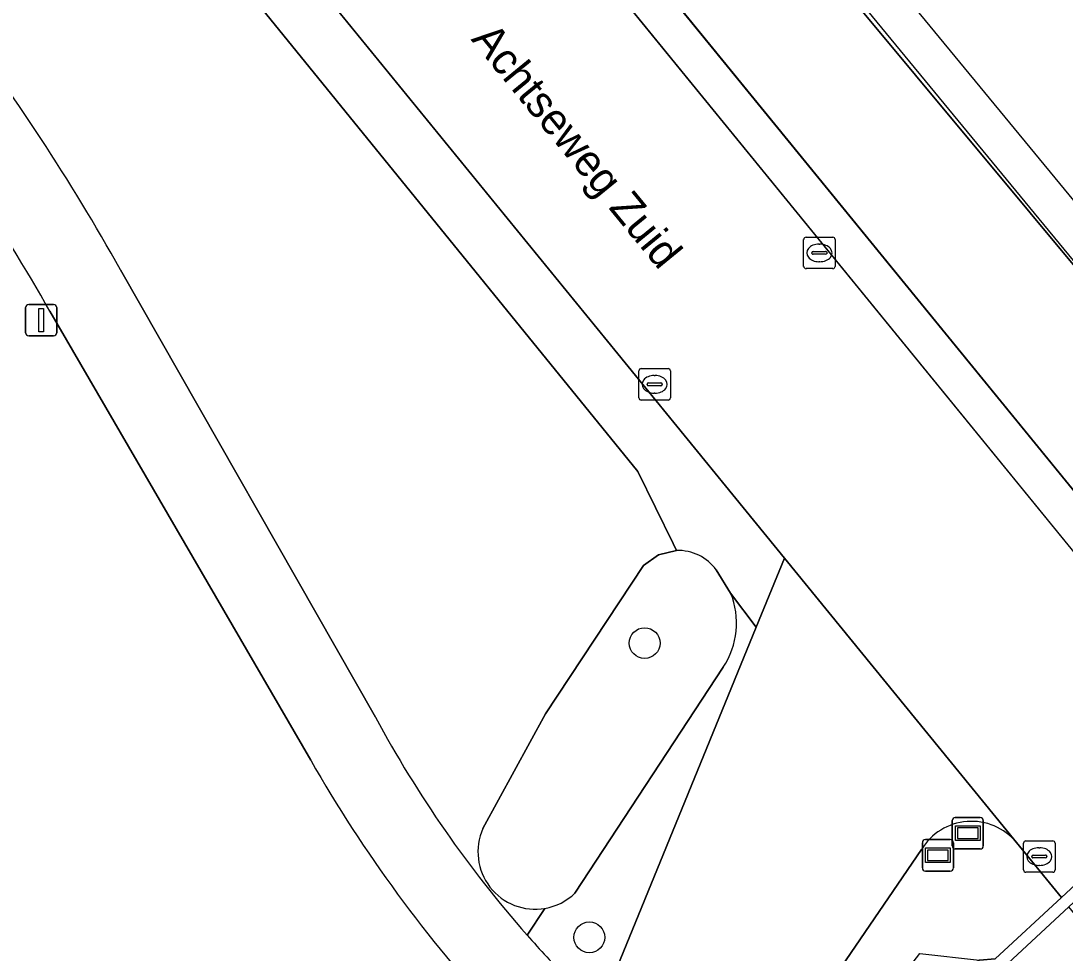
# Model space of a CAD drawing. Extents: x 157132 to 159279, y 384991 to 386650.
# Drawn here: x 159129.42 to 159162.63, y 385372.27 to 385401.9 of the extents above; entities that cross this region are included whole.
import ezdxf

# ---------------------------------------------------------------- set-up
doc = ezdxf.new("R2010")
doc.units = 0
for name, color, linetype in [('IMGEO_Boom', 7, 'Continuous'), ('IMGEO_Fietspad_gesloten', 7, 'Continuous'), ('IMGEO_Gemengd_bos', 7, 'Continuous'), ('IMGEO_Grasland_overig', 7, 'Continuous'), ('IMGEO_Groenvoorziening', 7, 'Continuous'), ('IMGEO_Hek', 7, 'Continuous'), ('IMGEO_Informatiebord', 7, 'Continuous'), ('IMGEO_Kolk', 7, 'Continuous'), ('IMGEO_Lichtmast', 7, 'Continuous'), ('IMGEO_Muur', 7, 'Continuous'), ('IMGEO_Openbare_ruimte_label', 7, 'Continuous'), ('IMGEO_Rijbaan_lokaal_open', 7, 'Continuous'), ('IMGEO_Spoorbaan_halfverhard', 7, 'Continuous'), ('IMGEO_Terreindeel_open', 7, 'Continuous'), ('IMGEO_Voetpad_open', 7, 'Continuous'), ('IMGEO_Waterloop', 7, 'Continuous')]:
    doc.layers.add(name, color=color, linetype=linetype)

msp = doc.modelspace()

# ---------------------------------------------------------------- linework, layer by layer
at = {"layer": 'IMGEO_Boom'}
for centre in [(159149.26, 385382.121), (159147.502, 385372.767)]:
    msp.add_circle(centre, 0.489, dxfattribs=at)
at = {"layer": 'IMGEO_Fietspad_gesloten'}
for points in [[(159140.697, 385379.765), (159132.59, 385393.989)], [(159130.342, 385392.676), (159138.639, 385378.397)]]:
    msp.add_lwpolyline(points, dxfattribs=at)
for centre, radius, start, end in [((159070.174, 385358.967), 71.57, 29.29683, 37.11613), ((159064.342, 385355.135), 75.929, 29.63123, 36.69187), ((159173.415, 385397.405), 37.17, 208.3324, 221.3679), ((159177.232, 385400.446), 44.448, 209.7395, 222.8211), ((159173.878, 385397.84), 37.805, 221.3976, 224.2452)]:
    msp.add_arc(centre, radius, start, end, dxfattribs=at)
at = {"layer": 'IMGEO_Gemengd_bos'}
for points in [[(159144.117, 385376.225), (159146.108, 385379.875), (159149.225, 385384.585), (159149.701, 385384.93), (159150.273, 385385.066), (159150.167, 385385.283), (159149.043, 385387.58), (159057.676, 385500), (159035.861, 385526.812), (159000, 385569.989), (158976.812, 385598.387), (158944.195, 385637.794), (158939.671, 385643.611), (158934.261, 385635.792)], [(159132.59, 385393.989), (159140.697, 385379.765)], [(159138.639, 385378.397), (159130.342, 385392.676)], [(159153.481, 385365.728), (159153.796, 385366.759), (159158.017, 385372.254), (159159.908, 385372.041), (159160.412, 385372.085), (159162.514, 385374.032), (159161.083, 385375.787)], [(159158.064, 385375.556), (159151.636, 385366.142), (159166.215, 385350.114), (159185.472, 385329.661), (159187.671, 385327.321)], [(159145.519, 385372.84), (159146.09, 385373.688)], [(159191.433, 385324.723), (159192.248, 385324.356), (159202.706, 385324.094), (159195.643, 385333.405), (159162.754, 385373.737), (159160.671, 385371.807), (159160.588, 385371.307), (159160.64, 385370.549), (159156.274, 385364.359)]]:
    msp.add_lwpolyline(points, dxfattribs=at)
for centre, radius, start, end in [((159070.174, 385358.967), 71.57, 29.29683, 37.11613), ((159064.342, 385355.135), 75.929, 29.63123, 36.69187), ((159173.415, 385397.405), 37.17, 208.3324, 221.3679), ((159177.232, 385400.446), 44.448, 209.7395, 222.8211), ((159159.656, 385374.597), 1.858, 39.8124, 148.9385), ((159145.778, 385375.481), 1.82, 155.8671, 279.8766)]:
    msp.add_arc(centre, radius, start, end, dxfattribs=at)
at = {"layer": 'IMGEO_Grasland_overig'}
for points in [[(159070.687, 385500), (159100.286, 385463.691), (159167.2, 385381.706), (159167.226, 385381.955), (159168.723, 385381.796), (159169.657, 385380.664), (159169.912, 385380.355), (159170.761, 385379.326), (159170.605, 385377.81), (159170.356, 385377.836), (159191.002, 385351.917), (159224.612, 385309.725)], [(159218.546, 385326.665), (159205.058, 385342.95), (159195.791, 385354.347), (159181.227, 385371.527), (159168.76, 385387.107), (159146.986, 385413.255), (159124.294, 385441.044), (159114.976, 385452.124), (159102.075, 385468.133), (159082.021, 385492.494)]]:
    msp.add_lwpolyline(points, dxfattribs=at)
at = {"layer": 'IMGEO_Groenvoorziening'}
msp.add_lwpolyline([(159167.2, 385381.706), (159100.286, 385463.691), (159070.687, 385500), (159044.807, 385531.748), (159011.046, 385573.162), (159010.937, 385573.296), (159000, 385586.793), (158885.494, 385728.344), (158857.155, 385763.115), (158856.922, 385762.926), (158855.151, 385763.341), (158855.067, 385763.287), (158854.563, 385763.33), (158854.381, 385763.213), (159043.862, 385530.978), (159167.844, 385378.971), (159168.01, 385379.124), (159168.092, 385379.623), (159168.34, 385381.585)], close=True, dxfattribs=at)
for points in [[(159151.54, 385384.447), (159151.995, 385383.713), (159152.806, 385382.628), (159153.706, 385384.827), (159038.204, 385526.376), (158938.905, 385648.068), (158937.569, 385646.098), (158938.459, 385644.928)], [(158939.803, 385643.802), (158939.671, 385643.611), (158944.195, 385637.794), (158976.812, 385598.387), (159000, 385569.989), (159035.861, 385526.812), (159057.676, 385500), (159149.043, 385387.58), (159150.167, 385385.283), (159150.273, 385385.066)], [(159146.796, 385371.462), (159147.791, 385370.368), (159152.806, 385382.628), (159151.995, 385383.713)], [(159151.762, 385381.355), (159147.041, 385374.171)], [(159146.09, 385373.688), (159145.519, 385372.84)]]:
    msp.add_lwpolyline(points, dxfattribs=at)
for centre, radius, start, end in [((159150.322, 385383.56), 1.507, 36.0685, 91.8553), ((159149.632, 385382.756), 2.55, 326.6707, 22.0428), ((159145.781, 385375.473), 1.812, 279.8049, 314.0459), ((159173.878, 385397.84), 37.805, 221.3976, 224.2452)]:
    msp.add_arc(centre, radius, start, end, dxfattribs=at)
at = {"layer": 'IMGEO_Hek'}
msp.add_lwpolyline([(159211.713, 385335.149), (159200.593, 385348.679), (159191.169, 385360.049), (159187.934, 385364.03), (159178.354, 385375.528), (159160.922, 385396.693), (159137.128, 385425.571), (159108.876, 385459.98), (159096.003, 385475.701), (159072.576, 385504.374)], dxfattribs=at)
at = {"layer": 'IMGEO_Informatiebord'}
for p, q in [((159159.042, 385375.678), (159159.042, 385376.478)), ((159159.042, 385376.478), (159159.042, 385375.678)), ((159159.142, 385376.578), (159159.932, 385376.578)), ((159159.932, 385376.578), (159159.142, 385376.578)), ((159160.032, 385376.478), (159160.032, 385375.678)), ((159160.032, 385375.678), (159160.032, 385376.478)), ((159158.093, 385374.976), (159158.093, 385375.776)), ((159158.093, 385375.776), (159158.093, 385374.976)), ((159158.193, 385375.876), (159158.983, 385375.876)), ((159158.983, 385375.876), (159158.193, 385375.876)), ((159159.083, 385375.776), (159159.083, 385374.976)), ((159159.083, 385374.976), (159159.083, 385375.776)), ((159159.932, 385375.578), (159159.142, 385375.578)), ((159159.142, 385375.578), (159159.932, 385375.578)), ((159158.983, 385374.876), (159158.193, 385374.876)), ((159158.193, 385374.876), (159158.983, 385374.876))]:
    msp.add_line(p, q, dxfattribs=at)
for points in [[(159159.143, 385376.31), (159159.931, 385376.31), (159159.931, 385375.846), (159159.143, 385375.846), (159159.143, 385376.31)], [(159159.208, 385376.245), (159159.208, 385375.911), (159159.866, 385375.911), (159159.866, 385376.245), (159159.208, 385376.245)], [(159158.194, 385375.608), (159158.982, 385375.608), (159158.982, 385375.144), (159158.194, 385375.144), (159158.194, 385375.608)], [(159158.259, 385375.543), (159158.259, 385375.209), (159158.917, 385375.209), (159158.917, 385375.543), (159158.259, 385375.543)]]:
    msp.add_lwpolyline(points, dxfattribs=at)
for centre, start, end in [((159159.142, 385376.478), 90, 180), ((159159.142, 385376.478), 90, 180), ((159159.932, 385376.478), 0, 90), ((159159.932, 385376.478), 360, 90), ((159158.193, 385375.776), 90, 180), ((159158.193, 385375.776), 90, 180), ((159158.983, 385375.776), 0, 90), ((159158.983, 385375.776), 360, 90), ((159159.142, 385375.678), 180, 270), ((159159.142, 385375.678), 180, 270), ((159159.932, 385375.678), 270, 0), ((159159.932, 385375.678), 270, 0), ((159158.193, 385374.976), 180, 270), ((159158.193, 385374.976), 180, 270), ((159158.983, 385374.976), 270, 0), ((159158.983, 385374.976), 270, 0)]:
    msp.add_arc(centre, 0.1, start, end, dxfattribs=at)
at = {"layer": 'IMGEO_Kolk'}
for p, q in [((159154.318, 385394.1), (159154.318, 385394.952)), ((159154.393, 385395.026), (159155.245, 385395.026)), ((159155.319, 385394.952), (159155.319, 385394.1)), ((159154.577, 385394.52), (159154.577, 385394.532)), ((159154.62, 385394.569), (159155.018, 385394.569)), ((159154.806, 385394.806), (159154.831, 385394.806)), ((159155.061, 385394.532), (159155.061, 385394.52)), ((159155.015, 385394.483), (159154.617, 385394.483)), ((159154.829, 385394.246), (159154.804, 385394.246)), ((159155.245, 385394.026), (159154.393, 385394.026)), ((159149.078, 385389.923), (159149.078, 385390.775)), ((159149.153, 385390.849), (159150.005, 385390.849)), ((159149.566, 385390.629), (159149.591, 385390.629)), ((159150.079, 385390.775), (159150.079, 385389.923)), ((159149.337, 385390.343), (159149.337, 385390.355)), ((159149.775, 385390.306), (159149.377, 385390.306)), ((159149.38, 385390.392), (159149.778, 385390.392)), ((159149.821, 385390.355), (159149.821, 385390.343)), ((159149.589, 385390.069), (159149.564, 385390.069)), ((159150.005, 385389.849), (159149.153, 385389.849)), ((159161.312, 385374.909), (159161.312, 385375.761)), ((159161.387, 385375.835), (159162.239, 385375.835)), ((159161.8, 385375.615), (159161.825, 385375.615)), ((159162.313, 385375.761), (159162.313, 385374.909)), ((159161.571, 385375.329), (159161.571, 385375.341)), ((159162.009, 385375.292), (159161.611, 385375.292)), ((159161.614, 385375.378), (159162.012, 385375.378)), ((159162.055, 385375.341), (159162.055, 385375.329)), ((159161.823, 385375.055), (159161.798, 385375.055)), ((159162.239, 385374.835), (159161.387, 385374.835))]:
    msp.add_line(p, q, dxfattribs=at)
for points in [[(159154.318, 385394.1), (159154.318, 385394.952)], [(159154.393, 385395.026), (159155.245, 385395.026)], [(159155.319, 385394.952), (159155.319, 385394.1)], [(159155.245, 385394.026), (159154.393, 385394.026)], [(159149.078, 385389.923), (159149.078, 385390.775)], [(159149.153, 385390.849), (159150.005, 385390.849)], [(159150.079, 385390.775), (159150.079, 385389.923)], [(159150.005, 385389.849), (159149.153, 385389.849)], [(159161.312, 385374.909), (159161.312, 385375.761)], [(159161.387, 385375.835), (159162.239, 385375.835)], [(159162.313, 385375.761), (159162.313, 385374.909)], [(159162.239, 385374.835), (159161.387, 385374.835)]]:
    msp.add_lwpolyline(points, dxfattribs=at)
for centre, radius, start, end in [((159154.395, 385394.95), 0.0765, 91.552, 178.448), ((159154.395, 385394.95), 0.0765, 91.552, 178.448), ((159155.243, 385394.95), 0.0765, 1.552, 88.448), ((159155.243, 385394.95), 0.0765, 1.552, 88.448), ((159154.617, 385394.529), 0.0403, 85.8775, 175.7526), ((159155.022, 385394.531), 0.0386, 1.7309, 96.639), ((159154.614, 385394.519), 0.0366, 178.938, 274.7102), ((159155.018, 385394.526), 0.043, 264.8664, 352.4533), ((159154.395, 385394.102), 0.0765, 181.552, 268.448), ((159154.395, 385394.102), 0.0765, 181.552, 268.448), ((159155.243, 385394.102), 0.0765, 271.552, 358.448), ((159155.243, 385394.102), 0.0765, 271.552, 358.448), ((159149.155, 385390.773), 0.0765, 91.552, 178.448), ((159149.155, 385390.773), 0.0765, 91.552, 178.448), ((159150.003, 385390.773), 0.0765, 1.552, 88.448), ((159150.003, 385390.773), 0.0765, 1.552, 88.448), ((159149.377, 385390.352), 0.0403, 85.8775, 175.7526), ((159149.374, 385390.342), 0.0366, 178.938, 274.7102), ((159149.778, 385390.349), 0.043, 264.8664, 352.4533), ((159149.782, 385390.354), 0.0386, 1.7309, 96.639), ((159149.155, 385389.925), 0.0765, 181.552, 268.448), ((159149.155, 385389.925), 0.0765, 181.552, 268.448), ((159150.003, 385389.925), 0.0765, 271.552, 358.448), ((159150.003, 385389.925), 0.0765, 271.552, 358.448), ((159161.389, 385375.759), 0.0765, 91.552, 178.448), ((159161.389, 385375.759), 0.0765, 91.552, 178.448), ((159162.237, 385375.759), 0.0765, 1.552, 88.448), ((159162.237, 385375.759), 0.0765, 1.552, 88.448), ((159161.611, 385375.338), 0.0403, 85.8775, 175.7526), ((159161.608, 385375.328), 0.0366, 178.938, 274.7102), ((159162.012, 385375.335), 0.043, 264.8664, 352.4533), ((159162.016, 385375.34), 0.0386, 1.7309, 96.639), ((159161.389, 385374.911), 0.0765, 181.552, 268.448), ((159161.389, 385374.911), 0.0765, 181.552, 268.448), ((159162.237, 385374.911), 0.0765, 271.552, 358.448), ((159162.237, 385374.911), 0.0765, 271.552, 358.448)]:
    msp.add_arc(centre, radius, start, end, dxfattribs=at)
for centre, major_axis, ratio, start_param, end_param in [((159154.805, 385394.526), (-0.387, 0.002), 0.722429, 4.712389, 7.853982), ((159154.83, 385394.526), (-0.39, 0.002), 0.717154, 1.570796, 4.712389), ((159149.565, 385390.349), (-0.387, 0.002), 0.722429, 4.712389, 7.853982), ((159149.59, 385390.349), (-0.39, 0.002), 0.717154, 1.570796, 4.712389), ((159161.799, 385375.335), (-0.387, 0.002), 0.722429, 4.712389, 7.853982), ((159161.824, 385375.335), (-0.39, 0.002), 0.717154, 1.570796, 4.712389)]:
    msp.add_ellipse(centre, major_axis=major_axis, ratio=ratio, start_param=start_param, end_param=end_param, dxfattribs=at)
at = {"layer": 'IMGEO_Lichtmast'}
for p, q in [((159129.671, 385392.889), (159130.461, 385392.889)), ((159130.461, 385392.889), (159129.671, 385392.889)), ((159129.571, 385391.989), (159129.571, 385392.789)), ((159129.571, 385392.789), (159129.571, 385391.989)), ((159130.561, 385392.789), (159130.561, 385391.989)), ((159130.561, 385391.989), (159130.561, 385392.789)), ((159130.461, 385391.889), (159129.671, 385391.889)), ((159129.671, 385391.889), (159130.461, 385391.889))]:
    msp.add_line(p, q, dxfattribs=at)
msp.add_lwpolyline([(159129.991, 385392.764), (159130.141, 385392.764), (159130.141, 385392.014), (159129.991, 385392.014), (159129.991, 385392.764)], dxfattribs=at)
for centre, start, end in [((159129.671, 385392.789), 90, 180), ((159129.671, 385392.789), 90, 180), ((159130.461, 385392.789), 0, 90), ((159130.461, 385392.789), 360, 90), ((159129.671, 385391.989), 180, 270), ((159129.671, 385391.989), 180, 270), ((159130.461, 385391.989), 270, 0), ((159130.461, 385391.989), 270, 0)]:
    msp.add_arc(centre, 0.1, start, end, dxfattribs=at)
at = {"layer": 'IMGEO_Muur'}
msp.add_lwpolyline([(159010.937, 385573.296), (159044.807, 385531.748), (159100.286, 385463.691), (159167.2, 385381.706), (159168.34, 385381.585), (159168.595, 385381.558), (159169.474, 385380.494), (159169.729, 385380.185), (159170.502, 385379.248), (159170.444, 385378.688), (159170.356, 385377.836), (159224.612, 385309.725), (159249.549, 385278.463)], dxfattribs=at)
at = {"layer": 'IMGEO_Rijbaan_lokaal_open'}
msp.add_lwpolyline([(159043.862, 385530.978), (158854.381, 385763.213), (158848.245, 385759.247), (158935.542, 385652.189), (158938.905, 385648.068), (159038.204, 385526.376), (159153.706, 385384.827), (159161.083, 385375.787), (159162.514, 385374.032), (159167.844, 385378.971)], close=True, dxfattribs=at)
at = {"layer": 'IMGEO_Spoorbaan_halfverhard'}
for points in [[(159271.993, 385263.89), (159112.858, 385456.897), (159008.488, 385585.237), (158922.412, 385696.17)], [(158959.648, 385644.849), (158984.94, 385614.139), (159014.573, 385576.309), (159028.074, 385559.753), (159041.625, 385542.602), (159042.082, 385542.991), (159049.811, 385533.48), (159049.516, 385533.221), (159060.741, 385519), (159082.021, 385492.494), (159102.075, 385468.133), (159114.976, 385452.124), (159124.294, 385441.044), (159146.986, 385413.255), (159168.76, 385387.107), (159181.227, 385371.527), (159195.791, 385354.347), (159205.058, 385342.95), (159218.546, 385326.665)]]:
    msp.add_lwpolyline(points, dxfattribs=at)
at = {"layer": 'IMGEO_Terreindeel_open'}
msp.add_lwpolyline([(159168.085, 385378.675), (159168.268, 385378.845), (159168.772, 385378.889), (159168.845, 385378.957), (159168.166, 385379.691), (159168.092, 385379.623), (159168.01, 385379.124), (159167.844, 385378.971), (159162.514, 385374.032), (159160.412, 385372.085), (159159.908, 385372.041), (159159.835, 385371.973), (159160.514, 385371.239), (159160.588, 385371.307), (159160.671, 385371.807), (159162.754, 385373.737)], close=True, dxfattribs=at)
at = {"layer": 'IMGEO_Voetpad_open'}
msp.add_lwpolyline([(159161.083, 385375.787), (159153.706, 385384.827), (159152.806, 385382.628), (159147.791, 385370.368), (159151.636, 385366.142), (159158.064, 385375.556)], dxfattribs=at)
msp.add_arc((159159.656, 385374.597), 1.858, 39.8124, 148.9385, dxfattribs=at)
at = {"layer": 'IMGEO_Waterloop'}
for points in [[(159150.273, 385385.066), (159149.701, 385384.93), (159149.225, 385384.585), (159146.108, 385379.875), (159144.117, 385376.225)], [(159151.995, 385383.713), (159151.54, 385384.447)], [(159147.041, 385374.171), (159151.762, 385381.355)]]:
    msp.add_lwpolyline(points, dxfattribs=at)
for centre, radius, start, end in [((159150.322, 385383.56), 1.507, 36.0685, 91.8553), ((159149.632, 385382.756), 2.55, 326.6707, 22.0428), ((159145.778, 385375.481), 1.82, 155.8671, 279.8766), ((159145.781, 385375.473), 1.812, 279.8049, 314.0459)]:
    msp.add_arc(centre, radius, start, end, dxfattribs=at)

# ---------------------------------------------------------------- texts
at = {"layer": 'IMGEO_Openbare_ruimte_label'}
msp.add_text('Achtseweg Zuid', height=1, rotation=309.2773, dxfattribs=at).set_placement((159143.717, 385401.311))

doc.saveas('drawing.dxf')
